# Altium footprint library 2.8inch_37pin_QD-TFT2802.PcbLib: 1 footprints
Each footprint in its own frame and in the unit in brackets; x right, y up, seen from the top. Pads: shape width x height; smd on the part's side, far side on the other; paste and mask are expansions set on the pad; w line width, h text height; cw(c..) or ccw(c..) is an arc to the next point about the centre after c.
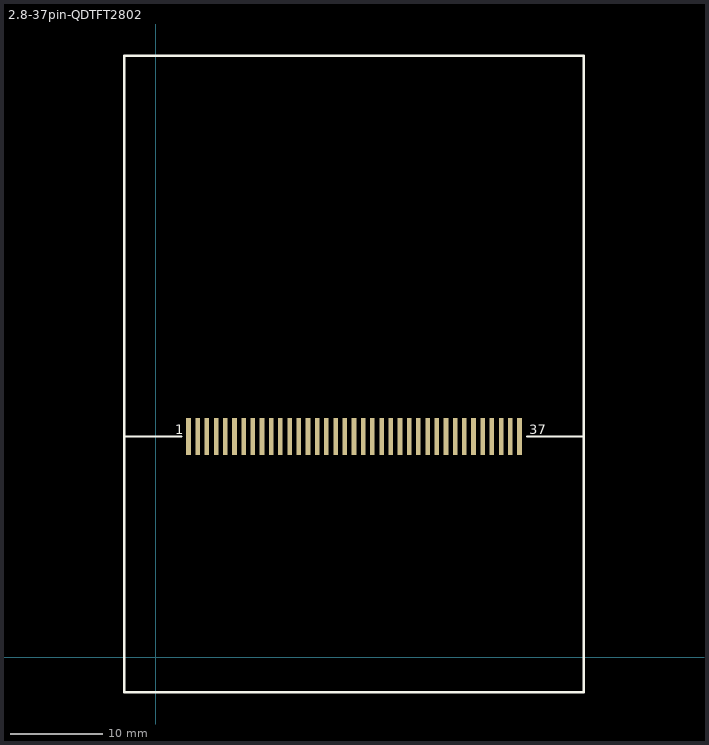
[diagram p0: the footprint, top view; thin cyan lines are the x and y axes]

## 2.8-37pin-QDTFT2802 [mm] "2.8 TFT"
pads (37):
  rect 0.5x4 smd: 1(3.571,23.99) 2(4.571,23.99) 3(5.571,23.99) 4(6.571,23.99) 5(7.571,23.99) 6(8.571,23.99) 7(9.571,23.99) 8(10.571,23.99) 9(11.571,23.99) 10(12.571,23.99) 11(13.571,23.99) 12(14.571,23.99) 13(15.571,23.99) 14(16.571,23.99) 15(17.571,23.99) 16(18.571,23.99) 17(19.571,23.99) 18(20.571,23.99) 19(21.571,23.99) 20(22.571,23.99) 21(23.571,23.99) 22(24.571,23.99) 23(25.571,23.99) 24(26.571,23.99) 25(27.571,23.99) 26(28.571,23.99) 27(29.571,23.99) 28(30.571,23.99) 29(31.571,23.99) 30(32.571,23.99) 31(33.571,23.99) 32(34.571,23.99) 33(35.571,23.99) 34(36.571,23.99) 35(37.571,23.99) 36(38.571,23.99) 37(39.571,23.99)
Top Overlay:
  lines w0.254: -3.429,23.99 2.794,23.99 ; 40.386,23.99 46.571,23.99 ; -3.429,-3.81 -3.429,65.39 46.571,65.39 46.571,-3.81 -3.429,-3.81
  text "1" at 2.159,24.257 h1.02
  text "37" at 40.64,24.257 h1.02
